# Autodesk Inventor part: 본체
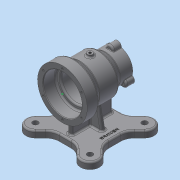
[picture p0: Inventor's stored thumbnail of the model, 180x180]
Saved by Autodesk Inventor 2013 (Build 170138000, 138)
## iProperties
Created: 2017-03
Part Number: 본체
Material: 일반
Document SubType Name: Modeling
Designer: Administrator
Density: 1 g/cm^3
Author: Administrator
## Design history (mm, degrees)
sketch "스케치1"
  geometry: 1 further point
sketch "스케치2"
  geometry: L1 (0, 0)-(100, 0); L2 (0, 35)-(23, 35); L3 (23, 35)-(23, 26); L4 (23, 26)-(70, 26); L5 (70, 26)-(70, 17.5); L6 (70, 17.5)-(100, 17.5); L7 (100, 17.5)-(100, 27.5); L8 (100, 27.5)-(77, 27.5); L9 (77, 27.5)-(65, 36); L10 (65, 36)-(31, 36); L11 (31, 36)-(20, 45); L12 (20, 45)-(0, 45); L13 (0, 45)-(0, 35)
  constraints: 26 end point, 8 parallel, 2 perpendicular, 2 point on line, 1 horizontal
  dimensions: "d0" = 100 distance of L1.start L1.end; "d1" = 35 diameter of L6 L1; "d2" = 52 diameter of L4 L1; "d3" = 70 diameter of L2 L1; "d4" = 55 diameter of L8 L1; "d5" = 72 diameter of L10 L1; "d6" = 90 diameter of L12 L1; "d7" = 23 distance between parallel lines of L3 L13; "d8" = 47 distance between parallel lines of L5 L3; "d9" = 20 distance of L11.end L12.end; "d10" = 31 distance from line of L10.end L13; "d11" = 65 distance from line of L13 L9.end; "d12" = 23 distance of L7.end L8.end
revolve "회전1" sketch "스케치2" stored, may be unused: angle "d13" = 90 deg
chamfer "모따기1" distance "d25" = 1; stored, may be unused: second distance "d26" = 2, angle "d27" = 45 deg
node "작업 평면1"
sketch "스케치4"
  geometry: L1 (45, 5)-(-45, 5); L2 (-45, 5)-(-45, 95); L3 (-45, 95)-(45, 95); L4 (45, 95)-(45, 5); L5 (45, 5)-(-45, 95); L6 (-45, 5)-(45, 95); 2 further points
  constraints: 12 end point, 2 midpoint, 2 parallel, 1 horizontal, 1 perpendicular
  dimensions: "d29" = 90 distance of L2.end L3.end; "d31" = 90 distance of L1.end L2.end; "d32" = 0 horizontal distance of point (0, 0) point (0, 50); "d33" = 50 distance of point (0, 0) point (0, 50)
extrude "돌출2" join sketch "스케치4" distance "d34" = 12; taper "d35" = 0 deg
sketch "스케치5" dims "d36" = 140
  geometry: L1 (45, 5)-(-45, 5) reference; L2 (45, 95)-(45, 5) reference; L3 (-45, 95)-(45, 95) reference; L4 (-45, 5)-(-45, 95) reference; L5 (-45, 50)-(45, 50); L6 (0, 95)-(0, 5); L7 (49.497, 99.497)-(0, 50); L8 (24.042, 50)-(61.518, 87.477); L9 (0, 74.042)-(37.477, 111.518); A1 r 17 centre (49.497, 99.497) between (37.477, 111.518) and (61.518, 87.477); 1 further point
  constraints: 10 end point, 5 midpoint, 2 point on circle, 2 point on line, 2 tangent, 1 centre point, 3 other
  dimensions: "d38" = 45 deg angle of L5 L7; "d40" = 34 diameter of A1; "d41" = 45 deg angle of L5 L8; "d42" = 45 deg angle of L6 L9
extrude "돌출3" join sketch "스케치5" distance "d43" = 12; taper "d44" = 0 deg
sketch "스케치6"
  geometry: L1 (-45, 5)-(45, 5) reference; L2 (45, 5)-(45, 95) reference; C1 r 0.5 at (0, 50); 1 further point
  constraints: 1 centre point
  dimensions: "d45" = 45 distance from line of L1 C1.centre; "d46" = 45 distance from line of L2 C1.centre; "d47" = 1 diameter of C1
extrude "돌출4" join sketch "스케치6" distance "d48" = 5; taper "d49" = 0 deg
fillet "모깎기3" dims "d53" = 25
fillet "모깎기4" dims "d54" = 3
fillet "모깎기5" dims "d55" = 3
chamfer "모따기2" distance "d56" = 1; stored, may be unused: second distance "d57" = 2, angle "d58" = 45 deg
node "작업 평면2"
sketch "스케치11"
  geometry: L1 (-4, 87)-(4, 87); L2 (4, 87)-(4, 13); L3 (4, 13)-(-4, 13); L4 (-4, 13)-(-4, 87); L5 (-4, 87)-(4, 13); L6 (4, 87)-(-4, 13); C1 r 0.5 at (0, 50) reference; 1 further point
  constraints: 12 end point, 2 midpoint, 2 parallel, 1 horizontal, 1 perpendicular
  dimensions: "d85" = 8 distance between parallel lines of L4 L2; "d87" = 74 distance between parallel lines of L1 L3
extrude "돌출7" join sketch "스케치11" stored distance "d88" = 8; taper "d89" = 0 deg
node "작업 평면3"
sketch "스케치12"
  geometry: L1 (-4, -70)-(4, -70) reference; L2 (4, -70)-(-4, -70) reference; L3 (-30.402, -70)-(-10.603, -70) reference; L4 (-39.598, -70)-(-30.402, -70) reference; L5 (-59.397, -70)-(-39.598, -70) reference; L6 (-50.201, -70)-(-59.397, -70) reference; L7 (-42, -70)-(-50.201, -70) reference; L8 (-50.201, -70)-(-42, -70) reference; L9 (-59.397, -70)-(-50.201, -70) reference; L10 (-39.598, -70)-(-59.397, -70) reference; L11 (-30.402, -70)-(-39.598, -70) reference; L12 (-10.603, -70)-(-30.402, -70) reference; L13 (10.603, -70)-(-10.603, -70) reference; L14 (30.402, -70)-(10.603, -70) reference; L15 (39.598, -70)-(30.402, -70) reference; L16 (59.397, -70)-(39.598, -70) reference; L17 (50.201, -70)-(59.397, -70) reference; L18 (42, -70)-(50.201, -70) reference; L19 (50.201, -70)-(42, -70) reference; L20 (59.397, -70)-(50.201, -70) reference; L21 (39.598, -70)-(59.397, -70) reference; L22 (30.402, -70)-(39.598, -70) reference; L23 (10.603, -70)-(30.402, -70) reference; L24 (-10.603, -70)-(10.603, -70) reference; L25 (-25, -70)-(-18.14, -31.096); A1 r 36 centre (0, 0) between (4, -35.777) and (-4, -35.777) reference; A2 r 36 centre (0, 0) between (4, -35.777) and (-4, -35.777) reference; 1 further point
  constraints: 2 end point, 2 point on circle, 1 point on line
  dimensions: "d91" = 25 horizontal distance of point (0, 0) L25.start; "d92" = 100 deg angle of L11 L25
feature "리브3" sketch "스케치12" dims "d93" = 1, "d94" = 4, "d95" = 0, "d96" = 0, "d97" = 1, "d98" = 1
sketch "스케치13"
  geometry: L1 (-10.603, -70)-(-30.402, -70) reference; L2 (-25, -70)-(-18.14, -31.096); A1 r 36 centre (0, 0) between (4, -35.777) and (-4, -35.777) reference; 1 further point
  constraints: 2 end point, 1 point on circle, 1 point on line
  dimensions: "d99" = 25 horizontal distance of point (0, 0) L2.start; "d100" = 100 deg angle of L1 L2
feature "리브4" sketch "스케치13" dims "d101" = 1, "d102" = 4, "d103" = 0, "d104" = 0, "d105" = 1, "d106" = 1
sketch "스케치14"
  geometry: L1 (30.402, -70)-(10.603, -70) reference; L2 (25, -70)-(18.14, -31.096); A1 r 36 centre (0, 0) between (4, -35.777) and (-4, -35.777) reference; 1 further point
  constraints: 2 end point, 1 point on circle, 1 point on line
  dimensions: "d107" = 25 horizontal distance of point (0, 0) L2.start; "d108" = 100 deg angle of L1 L2
feature "리브5" sketch "스케치14" dims "d109" = 1, "d110" = 4, "d111" = 0, "d112" = 0, "d113" = 1, "d114" = 1
sketch "스케치15"
  geometry: L1 (4, -70)-(25, -70) reference; L2 (30.402, -70)-(10.603, -70) reference; L3 (25, -70)-(18.14, -31.096); A1 r 36 centre (0, 0) between (4, -35.777) and (-4, -35.777) reference; 1 further point
  constraints: 2 end point, 1 point on circle, 1 point on line
  dimensions: "d115" = 25 horizontal distance of point (0, 0) L3.start; "d116" = 100 deg angle of L1 L3
feature "리브6" sketch "스케치15" dims "d117" = 1, "d118" = 4, "d119" = 0, "d120" = 0, "d121" = 1, "d122" = 1
fillet "모깎기8" dims "d123" = 3
fillet "모깎기9" dims "d124" = 3
fillet "모깎기10" dims "d125" = 3
fillet "모깎기11" dims "d126" = 3
fillet "모깎기12" dims "d127" = 3
sketch "스케치16"
  geometry: C1 r 5 at (-49.497, 0.503); C2 r 5 at (-49.497, 99.497); C3 r 5 at (49.497, 99.497); C4 r 5 at (49.497, 0.503); A1 r 14 centre (49.497, 99.497) between (59.397, 89.598) and (39.598, 109.397) reference; A2 r 14 centre (-49.497, 99.497) between (-39.598, 109.397) and (-59.397, 89.598) reference; A3 r 14 centre (-49.497, 0.503) between (-59.397, 10.402) and (-39.598, -9.397) reference; A4 r 14 centre (49.497, 0.503) between (39.598, -9.397) and (59.397, 10.402) reference; 1 further point
  constraints: 4 centre point, 4 coincident, 3 equal radius
  dimensions: "d128" = 10 diameter of C1
extrude "돌출8" cut sketch "스케치16" stored distance "d130" = 8; taper "d131" = 0 deg
sketch "스케치17"
  geometry: C1 r 27.5 at (0, 0) reference; C2 r 7 at (0, -27.5)
  constraints: 1 centre point
  dimensions: "d132" = 0 horizontal distance of C1.centre C2.centre; "d133" = 27.5 distance of C2.centre C1.centre; "d134" = 14 diameter of C2
extrude "돌출9" join sketch "스케치17" distance "d135" = 15; taper "d136" = 0 deg
fillet "모깎기13" dims "d140" = 3
fillet "모깎기14" dims "d141" = 1
node "작업 평면4"
sketch "스케치18"
  geometry: C1 r 5 at (0, 50); 1 further point
  constraints: 1 centre point
  dimensions: "d143" = 0 horizontal distance of point (0, 0) C1.centre; "d144" = 50 distance of C1.centre point (0, 0); "d145" = 10 diameter of C1
extrude "돌출10" join sketch "스케치18" stored distance "d146" = 4; taper "d147" = 0 deg
fillet "모깎기15" dims "d148" = 3
sketch "스케치19"
  geometry: C1 r 5 at (0, 0) reference; C2 r 2.5 at (0, 0); 1 further point
  constraints: 1 centre point, 1 coincident
  dimensions: "d149" = 5 diameter of C2
hole "구멍1" sketch "스케치19" at (0, 0) diameter "d151" = 4.459; stored, may be unused: countersink angle "d155" = 90 deg, drill point angle "d157" = 118 deg; dims "d152" = 6, "d153" = 4, "d154" = 2, "d156" = 8
sketch "스케치20"
  geometry: C1 r 45 at (0, 0) reference; C2 r 2 at (0, -40)
  constraints: 1 centre point
  dimensions: "d158" = 0 horizontal distance of C1.centre C2.centre; "d159" = 40 distance of C2.centre C1.centre; "d160" = 4 diameter of C2
hole "구멍2" sketch "스케치20" at (0, -40) diameter "d161" = 3.459; stored, may be unused: countersink angle "d165" = 90 deg, drill point angle "d167" = 118 deg; dims "d162" = 9, "d163" = 4, "d164" = 2, "d166" = 11
sketch "스케치21"
  geometry: L1 (1, 90)-(-1, 90) reference; L2 (27.517, 49)-(27.517, 51) reference; L3 (-1, 10)-(1, 10) reference; L4 (-27.517, 51)-(-27.517, 49) reference; L5 (56.927, 33.408)-(56.927, 66.592); L6 (56.927, 66.592)-(13.073, 66.592); L7 (13.073, 66.592)-(13.073, 33.408); L8 (13.073, 33.408)-(56.927, 33.408); L9 (35, 33.408)-(35, 66.592); L10 (13.073, 50)-(56.927, 50); L11 (0, 90)-(0, 10); L12 (27.517, 50)-(-27.517, 50); 1 further point
  constraints: 8 end point, 8 midpoint, 2 other
  dimensions: "d171" = 35 distance from line of point (0, 0) L9; "d173" = 0 distance between parallel lines of L12 L10
extrude "돌출11" join sketch "스케치21" distance "d174" = 0.5; taper "d175" = 0 deg
sketch "스케치22"
  geometry: C1 r 2 at (0, 0); A1 r 7 centre (0, 0) between (-6.999, 0.127) and (6.999, 0.127) reference
  constraints: 1 centre point, 1 coincident
  dimensions: "d176" = 4 diameter of C1
hole "구멍3" sketch "스케치22" at (0, 0) diameter "d178" = 3.459; stored, may be unused: countersink angle "d182" = 90 deg, drill point angle "d184" = 118 deg; dims "d179" = 9, "d180" = 4, "d181" = 2, "d183" = 11
node "솔리드1"
pattern_circular "원형 패턴2" dims angle "d51" = 360 deg
pattern_circular "원형 패턴3" dims angle "d138" = 360 deg
pattern_circular "원형 패턴4" dims angle "d169" = 360 deg
pattern_circular "원형 패턴5" dims angle "d186" = 360 deg
node "투영된 루프5"
node "투영된 루프6"
other parameters: "d28" = -82
